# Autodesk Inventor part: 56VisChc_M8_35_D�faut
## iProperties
Created: 2011-01
Part Number: 56VisChc_M8_35_D�faut
Document SubType Name: Modeling
Designer: eric
Density: 1 g/cm^3
Mass: 1.39036 g
Surface Area: 10.4193 cm^2
Volume: 1.39036 cm^3
Author: eric
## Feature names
1. Base1
